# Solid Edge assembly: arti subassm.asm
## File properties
Author: Vicky Raina
Template: Normal.asm
Last saved by: Robert a Rhodes jr
Revision: 14
Application: Solid Edge
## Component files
rod bush lower.par
rod bush upper.par
articulated rod.par
piston.par
piston pin.par
piston pin plug.par
piston ring.par
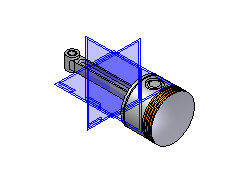
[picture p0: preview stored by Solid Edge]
